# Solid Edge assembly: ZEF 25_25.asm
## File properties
Title: Zylinder
Author: bmolnar
Template: iso metric assembly.asm
Last saved by: bmolnar
Revision: 12
Application: Solid Edge
Username: bmolnar
Dokumentum tartalom típus: 1
Document Number: ZEF 25/25
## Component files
Mutter.par
Profilrohr.par
Kolbenstange.par
Kit_2.par
Kit_1.par
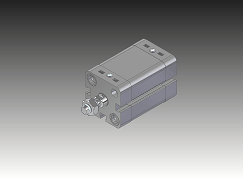
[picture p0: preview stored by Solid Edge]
